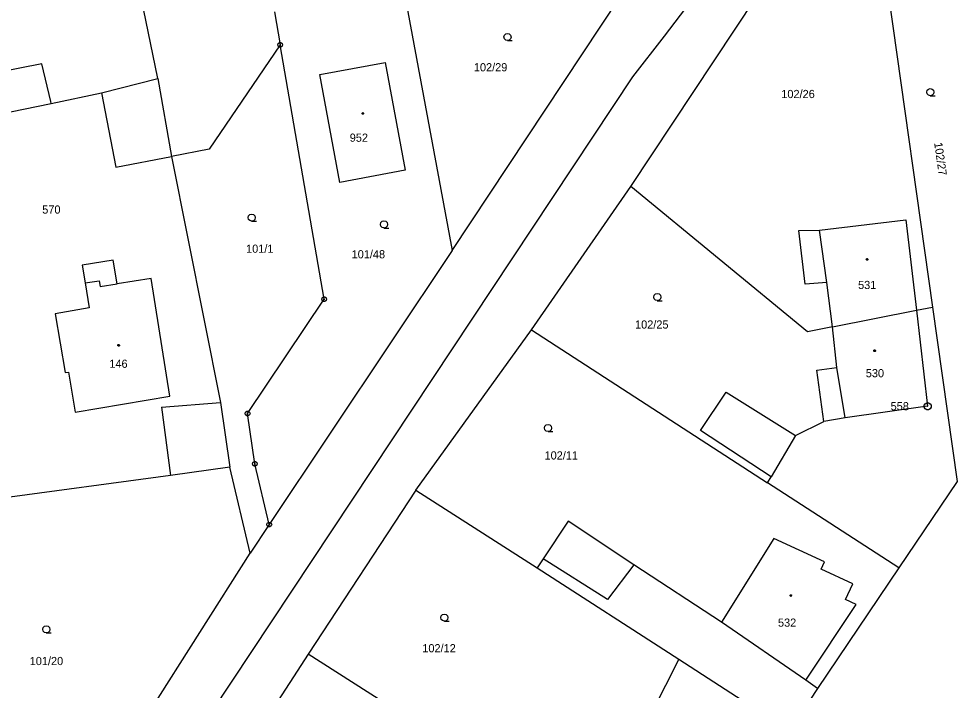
# Model space of a CAD drawing. Extents: x -757994 to -755874, y -1047691 to -1046119.
# Drawn here: x -756900.7 to -756803.8, y -1047154.8 to -1047085 of the extents above; entities that cross this region are included whole.
import ezdxf

# ---------------------------------------------------------------- set-up
doc = ezdxf.new("R2010")
doc.units = 0
doc.layers.add('katastrální mapa', color=7, linetype='Continuous')

msp = doc.modelspace()

# ---------------------------------------------------------------- linework, layer by layer
at = {"layer": 'katastrální mapa'}
for p, q in [((-756837.09, -1047102.42), (-756812.7, -1047065.66)), ((-756812.7, -1047065.66), (-756805.73, -1047114.96)), ((-756855.63, -1047109.07), (-756834.43, -1047077.05)), ((-756860.7, -1047081.77), (-756855.63, -1047109.07)), ((-756886.22, -1047091.19), (-756887.7, -1047083.94)), ((-756874.09, -1047084.25), (-756873.51, -1047087.71)), ((-756873.51, -1047087.71), (-756880.87, -1047098.55)), ((-756873.57, -1047087.71), (-756873.45, -1047087.71)), ((-756868.94, -1047114.13), (-756873.51, -1047087.71)), ((-756898.26, -1047089.67), (-756909.74, -1047091.94)), ((-756897.34, -1047093.6), (-756898.26, -1047089.67)), ((-756869.39, -1047090.78), (-756862.59, -1047089.52)), ((-756862.59, -1047089.52), (-756860.51, -1047100.72)), ((-756892.06, -1047092.7), (-756886.22, -1047091.19)), ((-756888.25, -1047168.55), (-756836.87, -1047091.03)), ((-756886.22, -1047091.19), (-756884.8, -1047099.31)), ((-756867.3, -1047101.99), (-756869.39, -1047090.78)), ((-756897.3, -1047093.79), (-756892.06, -1047092.7)), ((-756892.06, -1047092.7), (-756890.58, -1047100.42)), ((-756908.88, -1047096.19), (-756897.3, -1047093.79)), ((-756897.3, -1047093.79), (-756897.34, -1047093.6)), ((-756880.87, -1047098.55), (-756884.8, -1047099.31)), ((-756890.58, -1047100.42), (-756884.8, -1047099.31)), ((-756884.8, -1047099.31), (-756879.71, -1047124.88)), ((-756860.51, -1047100.72), (-756867.3, -1047101.99)), ((-756847.4, -1047117.31), (-756837.09, -1047102.42)), ((-756818.73, -1047117.54), (-756837.09, -1047102.42)), ((-756817.49, -1047106.96), (-756808.5, -1047105.88)), ((-756808.5, -1047105.88), (-756807.4, -1047115.29)), ((-756819.62, -1047107.01), (-756817.49, -1047106.96)), ((-756818.98, -1047112.58), (-756819.62, -1047107.01)), ((-756816.71, -1047112.39), (-756817.49, -1047106.96)), ((-756855.63, -1047109.07), (-756874.64, -1047137.57)), ((-756890.84, -1047110.08), (-756894.06, -1047110.59)), ((-756894.06, -1047110.59), (-756893.76, -1047112.45)), ((-756890.45, -1047112.53), (-756890.84, -1047110.08)), ((-756893.76, -1047112.45), (-756892.3, -1047112.22)), ((-756893.76, -1047112.45), (-756893.35, -1047115.02)), ((-756892.3, -1047112.22), (-756892.2, -1047112.8)), ((-756892.2, -1047112.8), (-756890.45, -1047112.53)), ((-756886.92, -1047111.97), (-756890.45, -1047112.53)), ((-756884.97, -1047124.22), (-756886.92, -1047111.97)), ((-756816.71, -1047112.39), (-756818.98, -1047112.58)), ((-756816.11, -1047117.02), (-756816.71, -1047112.39)), ((-756876.89, -1047126.02), (-756868.94, -1047114.13)), ((-756869, -1047114.13), (-756868.88, -1047114.13)), ((-756893.35, -1047115.02), (-756896.88, -1047115.64)), ((-756816.11, -1047117.02), (-756807.4, -1047115.29)), ((-756807.4, -1047115.29), (-756805.73, -1047114.96)), ((-756807.4, -1047115.29), (-756806.24, -1047125.26)), ((-756805.73, -1047114.96), (-756803.17, -1047133.07)), ((-756896.88, -1047115.64), (-756895.86, -1047121.77)), ((-756859.4, -1047133.97), (-756847.4, -1047117.31)), ((-756847.4, -1047117.31), (-756822.88, -1047133.21)), ((-756816.11, -1047117.02), (-756818.73, -1047117.54)), ((-756815.67, -1047121.22), (-756816.11, -1047117.02)), ((-756817.77, -1047121.5), (-756815.67, -1047121.22)), ((-756814.81, -1047126.45), (-756815.67, -1047121.22)), ((-756895.86, -1047121.77), (-756895.51, -1047121.71)), ((-756895.51, -1047121.71), (-756894.81, -1047125.88)), ((-756817.01, -1047126.85), (-756817.77, -1047121.5)), ((-756829.83, -1047127.77), (-756827.17, -1047123.79)), ((-756827.17, -1047123.79), (-756819.96, -1047128.32)), ((-756894.81, -1047125.88), (-756884.97, -1047124.22)), ((-756885.85, -1047125.35), (-756879.71, -1047124.88)), ((-756879.71, -1047124.88), (-756878.75, -1047131.61)), ((-756885.85, -1047125.35), (-756884.91, -1047132.45)), ((-756876.95, -1047126.02), (-756876.83, -1047126.02)), ((-756876.13, -1047131.26), (-756876.89, -1047126.02)), ((-756806.24, -1047125.26), (-756814.81, -1047126.45)), ((-756806.265, -1047125.26), (-756806.215, -1047125.26)), ((-756819.96, -1047128.32), (-756817.01, -1047126.85)), ((-756814.81, -1047126.45), (-756817.01, -1047126.85)), ((-756822.51, -1047132.59), (-756829.83, -1047127.77)), ((-756819.96, -1047128.32), (-756822.51, -1047132.59)), ((-756878.75, -1047131.61), (-756884.91, -1047132.45)), ((-756876.63, -1047140.55), (-756878.75, -1047131.61)), ((-756876.19, -1047131.26), (-756876.07, -1047131.26)), ((-756874.64, -1047137.57), (-756876.13, -1047131.26)), ((-756884.91, -1047132.45), (-756913.46, -1047136.34)), ((-756822.88, -1047133.21), (-756822.51, -1047132.59)), ((-756809.22, -1047142.06), (-756822.88, -1047133.21)), ((-756803.17, -1047133.07), (-756809.22, -1047142.06)), ((-756859.4, -1047133.97), (-756870.59, -1047151.05)), ((-756859.4, -1047133.97), (-756846.82, -1047142.07)), ((-756874.64, -1047137.57), (-756876.63, -1047140.55)), ((-756874.7, -1047137.57), (-756874.58, -1047137.57)), ((-756843.58, -1047137.2), (-756846.2, -1047141.14)), ((-756836.77, -1047141.74), (-756843.58, -1047137.2)), ((-756822.22, -1047139.01), (-756827.65, -1047147.7)), ((-756816.95, -1047141.44), (-756822.22, -1047139.01)), ((-756891.22, -1047163.49), (-756876.63, -1047140.55)), ((-756846.2, -1047141.14), (-756846.82, -1047142.07)), ((-756839.51, -1047145.36), (-756846.2, -1047141.14)), ((-756817.3, -1047142.21), (-756816.95, -1047141.44)), ((-756846.82, -1047142.07), (-756832.08, -1047151.57)), ((-756836.77, -1047141.74), (-756839.51, -1047145.36)), ((-756827.65, -1047147.7), (-756836.77, -1047141.74)), ((-756809.22, -1047142.06), (-756817.67, -1047154.61)), ((-756814.03, -1047143.71), (-756817.3, -1047142.21)), ((-756814.79, -1047145.35), (-756814.03, -1047143.71)), ((-756813.65, -1047145.87), (-756814.79, -1047145.35)), ((-756818.91, -1047153.75), (-756813.65, -1047145.87)), ((-756818.91, -1047153.75), (-756827.65, -1047147.7)), ((-756870.59, -1047151.05), (-756884.33, -1047172.13)), ((-756854.47, -1047161.31), (-756870.59, -1047151.05)), ((-756832.08, -1047151.57), (-756835.14, -1047157.54)), ((-756832.08, -1047151.57), (-756820.6, -1047158.97)), ((-756817.67, -1047154.61), (-756818.91, -1047153.75)), ((-756817.67, -1047154.61), (-756820.6, -1047158.97))]:
    msp.add_line(p, q, dxfattribs=at)
for points in [[(-756836.87, -1047091.03), (-756833.565, -1047086.796), (-756829.818, -1047081.821), (-756826.157, -1047076.783), (-756822.582, -1047071.683), (-756819.095, -1047066.523), (-756815.697, -1047061.304), (-756812.389, -1047056.027), (-756809.171, -1047050.694), (-756806.046, -1047045.308), (-756803.013, -1047039.868), (-756800.073, -1047034.377), (-756797.228, -1047028.837), (-756794.478, -1047023.249), (-756792.19, -1047018.39), (-756789.974, -1047013.53), (-756787.51, -1047007.873), (-756785.142, -1047002.176), (-756782.871, -1046996.44), (-756780.99, -1046991.44)], [(-756849.89, -1047087.25), (-756850.08, -1047087.2), (-756850.215, -1047087.065), (-756850.265, -1047086.88), (-756850.215, -1047086.695), (-756850.08, -1047086.56), (-756849.895, -1047086.51), (-756849.71, -1047086.56), (-756849.575, -1047086.695), (-756849.525, -1047086.885), (-756849.575, -1047087.075), (-756849.71, -1047087.21), (-756849.9, -1047087.26), (-756849.4, -1047087.26)], [(-756805.96, -1047092.98), (-756806.15, -1047092.93), (-756806.285, -1047092.795), (-756806.335, -1047092.61), (-756806.285, -1047092.425), (-756806.15, -1047092.29), (-756805.965, -1047092.24), (-756805.78, -1047092.29), (-756805.645, -1047092.425), (-756805.595, -1047092.615), (-756805.645, -1047092.805), (-756805.78, -1047092.94), (-756805.97, -1047092.99), (-756805.47, -1047092.99)], [(-756876.46, -1047106.02), (-756876.65, -1047105.97), (-756876.785, -1047105.835), (-756876.835, -1047105.65), (-756876.785, -1047105.465), (-756876.65, -1047105.33), (-756876.465, -1047105.28), (-756876.28, -1047105.33), (-756876.145, -1047105.465), (-756876.095, -1047105.655), (-756876.145, -1047105.845), (-756876.28, -1047105.98), (-756876.47, -1047106.03), (-756875.97, -1047106.03)], [(-756862.72, -1047106.73), (-756862.91, -1047106.68), (-756863.045, -1047106.545), (-756863.095, -1047106.36), (-756863.045, -1047106.175), (-756862.91, -1047106.04), (-756862.725, -1047105.99), (-756862.54, -1047106.04), (-756862.405, -1047106.175), (-756862.355, -1047106.365), (-756862.405, -1047106.555), (-756862.54, -1047106.69), (-756862.73, -1047106.74), (-756862.23, -1047106.74)], [(-756834.32, -1047114.28), (-756834.51, -1047114.23), (-756834.645, -1047114.095), (-756834.695, -1047113.91), (-756834.645, -1047113.725), (-756834.51, -1047113.59), (-756834.325, -1047113.54), (-756834.14, -1047113.59), (-756834.005, -1047113.725), (-756833.955, -1047113.915), (-756834.005, -1047114.105), (-756834.14, -1047114.24), (-756834.33, -1047114.29), (-756833.83, -1047114.29)], [(-756845.67, -1047127.89), (-756845.86, -1047127.84), (-756845.995, -1047127.705), (-756846.045, -1047127.52), (-756845.995, -1047127.335), (-756845.86, -1047127.2), (-756845.675, -1047127.15), (-756845.49, -1047127.2), (-756845.355, -1047127.335), (-756845.305, -1047127.525), (-756845.355, -1047127.715), (-756845.49, -1047127.85), (-756845.68, -1047127.9), (-756845.18, -1047127.9)], [(-756856.44, -1047147.6), (-756856.63, -1047147.55), (-756856.765, -1047147.415), (-756856.815, -1047147.23), (-756856.765, -1047147.045), (-756856.63, -1047146.91), (-756856.445, -1047146.86), (-756856.26, -1047146.91), (-756856.125, -1047147.045), (-756856.075, -1047147.235), (-756856.125, -1047147.425), (-756856.26, -1047147.56), (-756856.45, -1047147.61), (-756855.95, -1047147.61)], [(-756897.79, -1047148.82), (-756897.98, -1047148.77), (-756898.115, -1047148.635), (-756898.165, -1047148.45), (-756898.115, -1047148.265), (-756897.98, -1047148.13), (-756897.795, -1047148.08), (-756897.61, -1047148.13), (-756897.475, -1047148.265), (-756897.425, -1047148.455), (-756897.475, -1047148.645), (-756897.61, -1047148.78), (-756897.8, -1047148.83), (-756897.3, -1047148.83)]]:
    msp.add_lwpolyline(points, dxfattribs=at)
for points in [[(-756873.435, -1047087.47), (-756873.31, -1047087.56), (-756873.26, -1047087.705), (-756873.31, -1047087.85), (-756873.435, -1047087.94), (-756873.59, -1047087.94), (-756873.715, -1047087.85), (-756873.765, -1047087.705), (-756873.715, -1047087.56), (-756873.59, -1047087.47)], [(-756864.92, -1047094.745), (-756864.87, -1047094.755), (-756864.845, -1047094.8), (-756864.835, -1047094.83), (-756864.845, -1047094.875), (-756864.885, -1047094.91), (-756864.92, -1047094.915), (-756864.965, -1047094.9), (-756864.995, -1047094.87), (-756865.005, -1047094.83), (-756864.995, -1047094.785), (-756864.955, -1047094.75)], [(-756812.53, -1047109.915), (-756812.48, -1047109.925), (-756812.455, -1047109.97), (-756812.445, -1047110), (-756812.455, -1047110.045), (-756812.495, -1047110.08), (-756812.53, -1047110.085), (-756812.575, -1047110.07), (-756812.605, -1047110.04), (-756812.615, -1047110), (-756812.605, -1047109.955), (-756812.565, -1047109.92)], [(-756868.865, -1047113.89), (-756868.74, -1047113.98), (-756868.69, -1047114.125), (-756868.74, -1047114.27), (-756868.865, -1047114.36), (-756869.02, -1047114.36), (-756869.145, -1047114.27), (-756869.195, -1047114.125), (-756869.145, -1047113.98), (-756869.02, -1047113.89)], [(-756890.29, -1047118.845), (-756890.24, -1047118.855), (-756890.215, -1047118.9), (-756890.205, -1047118.93), (-756890.215, -1047118.975), (-756890.255, -1047119.01), (-756890.29, -1047119.015), (-756890.335, -1047119), (-756890.365, -1047118.97), (-756890.375, -1047118.93), (-756890.365, -1047118.885), (-756890.325, -1047118.85)], [(-756811.74, -1047119.405), (-756811.69, -1047119.415), (-756811.665, -1047119.46), (-756811.655, -1047119.49), (-756811.665, -1047119.535), (-756811.705, -1047119.57), (-756811.74, -1047119.575), (-756811.785, -1047119.56), (-756811.815, -1047119.53), (-756811.825, -1047119.49), (-756811.815, -1047119.445), (-756811.775, -1047119.41)], [(-756806.145, -1047124.9), (-756805.975, -1047124.995), (-756805.88, -1047125.165), (-756805.88, -1047125.36), (-756805.975, -1047125.53), (-756806.145, -1047125.625), (-756806.34, -1047125.625), (-756806.51, -1047125.53), (-756806.605, -1047125.36), (-756806.605, -1047125.165), (-756806.51, -1047124.995), (-756806.34, -1047124.9)], [(-756876.815, -1047125.78), (-756876.69, -1047125.87), (-756876.64, -1047126.015), (-756876.69, -1047126.16), (-756876.815, -1047126.25), (-756876.97, -1047126.25), (-756877.095, -1047126.16), (-756877.145, -1047126.015), (-756877.095, -1047125.87), (-756876.97, -1047125.78)], [(-756876.055, -1047131.02), (-756875.93, -1047131.11), (-756875.88, -1047131.255), (-756875.93, -1047131.4), (-756876.055, -1047131.49), (-756876.21, -1047131.49), (-756876.335, -1047131.4), (-756876.385, -1047131.255), (-756876.335, -1047131.11), (-756876.21, -1047131.02)], [(-756874.565, -1047137.33), (-756874.44, -1047137.42), (-756874.39, -1047137.565), (-756874.44, -1047137.71), (-756874.565, -1047137.8), (-756874.72, -1047137.8), (-756874.845, -1047137.71), (-756874.895, -1047137.565), (-756874.845, -1047137.42), (-756874.72, -1047137.33)], [(-756820.45, -1047144.855), (-756820.4, -1047144.865), (-756820.375, -1047144.91), (-756820.365, -1047144.94), (-756820.375, -1047144.985), (-756820.415, -1047145.02), (-756820.45, -1047145.025), (-756820.495, -1047145.01), (-756820.525, -1047144.98), (-756820.535, -1047144.94), (-756820.525, -1047144.895), (-756820.485, -1047144.86)]]:
    msp.add_lwpolyline(points, close=True, dxfattribs=at)

# ---------------------------------------------------------------- texts
for s, p in [('102/29', (-756853.384, -1047090.45)), ('102/26', (-756821.444, -1047093.23)), ('952', (-756866.281, -1047097.77)), ('570', (-756898.224, -1047105.24)), ('101/1', (-756877.048, -1047109.31)), ('101/48', (-756866.084, -1047109.89)), ('531', (-756813.47, -1047113.08)), ('102/25', (-756836.638, -1047117.19)), ('146', (-756891.253, -1047121.27)), ('530', (-756812.667, -1047122.25)), ('558', (-756810.087, -1047125.685)), ('102/11', (-756846.039, -1047130.8)), ('532', (-756821.791, -1047148.18)), ('102/12', (-756858.74, -1047150.84)), ('101/20', (-756899.527, -1047152.17))]:
    msp.add_text(s, height=0.85, dxfattribs=at).set_placement(p)
msp.add_text('102/27', height=0.85, rotation=278.17101, dxfattribs=at).set_placement((-756805.568, -1047097.896))

doc.saveas('drawing.dxf')
